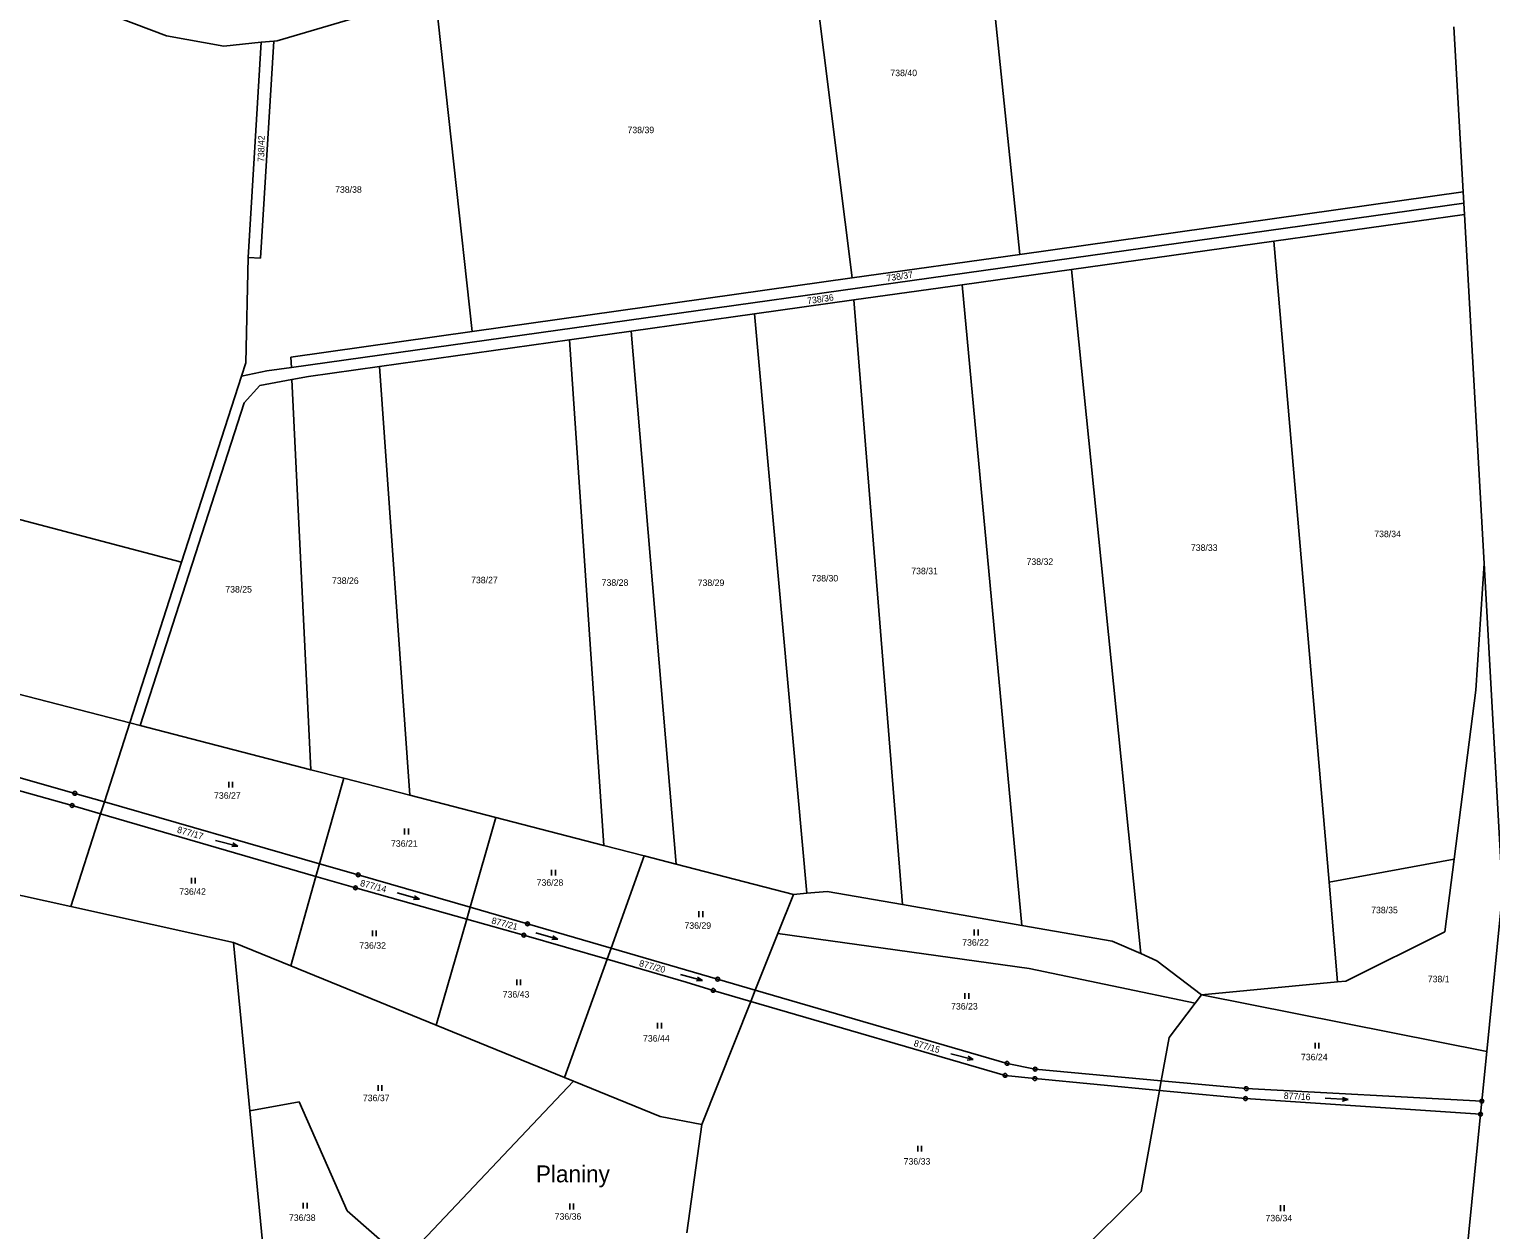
# Model space of a CAD drawing. Extents: x -791032 to -787751, y -1106872 to -1104403.
# Drawn here: x -789976.3 to -789595.2, y -1106360.1 to -1106046.8 of the extents above; entities that cross this region are included whole.
import ezdxf

# ---------------------------------------------------------------- set-up
doc = ezdxf.new("R2010")
doc.units = 0
for name, color, linetype in [('Vrstva 1', 7, 'Continuous'), ('Vrstva 14', 7, 'Continuous'), ('Vrstva 23', 7, 'Continuous'), ('Vrstva 28', 7, 'Continuous'), ('Vrstva 39', 7, 'Continuous')]:
    doc.layers.add(name, color=color, linetype=linetype)

msp = doc.modelspace()

# ---------------------------------------------------------------- linework, layer by layer
at = {"layer": 'Vrstva 1'}
for p, q in [((-789729.27, -1105996.01), (-789718.03, -1106105.57)), ((-789774.56, -1106009.37), (-789761.76, -1106111.73)), ((-789970.25, -1106037.29), (-789940.57, -1106048.55)), ((-789911.71, -1106049.84), (-789870.49, -1106037.68)), ((-789870.49, -1106037.68), (-789860.85, -1106125.71)), ((-789940.57, -1106048.55), (-789925.59, -1106051.2)), ((-789602.38, -1106089.26), (-789604.8, -1106046.21)), ((-789925.59, -1106051.2), (-789915.84, -1106050.24)), ((-789915.84, -1106050.24), (-789919.23, -1106106.35)), ((-789912.51, -1106049.92), (-789916, -1106106.52)), ((-789915.84, -1106050.24), (-789912.51, -1106049.92)), ((-789912.51, -1106049.92), (-789911.71, -1106049.84)), ((-789602.38, -1106089.26), (-789718.03, -1106105.57)), ((-789602.22, -1106092.2), (-789602.38, -1106089.26)), ((-789602.22, -1106092.2), (-789755.36, -1106113.66)), ((-789602.06, -1106095.13), (-789602.22, -1106092.2)), ((-789602.06, -1106095.13), (-789651.77, -1106102.1)), ((-789596.95, -1106186.19), (-789602.06, -1106095.13)), ((-789651.77, -1106102.1), (-789704.54, -1106109.5)), ((-789651.77, -1106102.1), (-789637.38, -1106269.41)), ((-789919.88, -1106133.86), (-789919.23, -1106106.35)), ((-789919.23, -1106106.35), (-789916, -1106106.52)), ((-789718.03, -1106105.57), (-789761.76, -1106111.73)), ((-789704.54, -1106109.5), (-789733.04, -1106113.49)), ((-789686.47, -1106288.01), (-789704.54, -1106109.5)), ((-789755.36, -1106113.66), (-789907.97, -1106135.04)), ((-789761.76, -1106111.73), (-789860.85, -1106125.71)), ((-789733.04, -1106113.49), (-789761.29, -1106117.45)), ((-789717.48, -1106280.63), (-789733.04, -1106113.49)), ((-789761.29, -1106117.45), (-789787.17, -1106121.08)), ((-789748.62, -1106275.21), (-789761.29, -1106117.45)), ((-789787.17, -1106121.08), (-789819.35, -1106125.59)), ((-789773.57, -1106272.27), (-789787.17, -1106121.08)), ((-789819.35, -1106125.59), (-789835.47, -1106127.85)), ((-789807.59, -1106264.69), (-789819.35, -1106125.59)), ((-789860.85, -1106125.71), (-789908.1, -1106132.37)), ((-789835.47, -1106127.85), (-789884.96, -1106134.79)), ((-789826.51, -1106259.79), (-789835.47, -1106127.85)), ((-789908.1, -1106132.37), (-789907.97, -1106135.04)), ((-789921, -1106137.35), (-789919.88, -1106133.86)), ((-789921, -1106137.35), (-789914.34, -1106135.94)), ((-789907.97, -1106135.04), (-789914.34, -1106135.94)), ((-789884.96, -1106134.79), (-789903.52, -1106137.39)), ((-789877.06, -1106246.71), (-789884.96, -1106134.79)), ((-789936.6, -1106185.85), (-789921, -1106137.35)), ((-789920.24, -1106144.27), (-789916.19, -1106139.81)), ((-789916.19, -1106139.81), (-789907.81, -1106138.21)), ((-789907.81, -1106138.21), (-789903.52, -1106137.39)), ((-789902.86, -1106240.04), (-789907.81, -1106138.21)), ((-789947.38, -1106228.52), (-789920.24, -1106144.27)), ((-790036.17, -1106159.75), (-789936.6, -1106185.85)), ((-789950.1, -1106227.82), (-789936.6, -1106185.85)), ((-789599.07, -1106219.3), (-789596.95, -1106186.19)), ((-789592.13, -1106272.11), (-789596.95, -1106186.19)), ((-789950.1, -1106227.82), (-790019.05, -1106209.98)), ((-789604.74, -1106263.35), (-789599.07, -1106219.3)), ((-789956.72, -1106248.41), (-789950.1, -1106227.82)), ((-789947.38, -1106228.52), (-789950.1, -1106227.82)), ((-790023.77, -1106229.41), (-789964.43, -1106246.19)), ((-789902.86, -1106240.04), (-789947.38, -1106228.52)), ((-789965.16, -1106249.35), (-790024.57, -1106232.72)), ((-789894.31, -1106242.25), (-789902.86, -1106240.04)), ((-789900.62, -1106264.57), (-789894.31, -1106242.25)), ((-789877.06, -1106246.71), (-789894.31, -1106242.25)), ((-789964.43, -1106246.19), (-789956.72, -1106248.41)), ((-789854.63, -1106252.52), (-789877.06, -1106246.71)), ((-789957.72, -1106251.51), (-789965.16, -1106249.35)), ((-789957.72, -1106251.51), (-789956.72, -1106248.41)), ((-789956.72, -1106248.41), (-789900.62, -1106264.57)), ((-789965.5, -1106275.69), (-789957.72, -1106251.51)), ((-789901.55, -1106267.86), (-789957.72, -1106251.51)), ((-789861.35, -1106275.92), (-789854.63, -1106252.52)), ((-789826.51, -1106259.79), (-789854.63, -1106252.52)), ((-789965.5, -1106275.69), (-790031.46, -1106261.12)), ((-789815.97, -1106262.52), (-789826.51, -1106259.79)), ((-789824.61, -1106286.59), (-789815.97, -1106262.52)), ((-789807.59, -1106264.69), (-789815.97, -1106262.52)), ((-789901.55, -1106267.86), (-789900.62, -1106264.57)), ((-789900.62, -1106264.57), (-789890.54, -1106267.47)), ((-789777.05, -1106272.59), (-789807.59, -1106264.69)), ((-789637.38, -1106269.41), (-789604.74, -1106263.35)), ((-789607.18, -1106282.34), (-789604.74, -1106263.35)), ((-789908.13, -1106291.16), (-789901.55, -1106267.86)), ((-789891.26, -1106270.86), (-789901.55, -1106267.86)), ((-789890.54, -1106267.47), (-789861.35, -1106275.92)), ((-789635.14, -1106295.41), (-789637.38, -1106269.41)), ((-789862.24, -1106279.01), (-789891.26, -1106270.86)), ((-789781.08, -1106282.72), (-789777.05, -1106272.59)), ((-789773.57, -1106272.27), (-789777.05, -1106272.59)), ((-789768.29, -1106271.79), (-789773.57, -1106272.27)), ((-789748.62, -1106275.21), (-789768.29, -1106271.79)), ((-789596.25, -1106313.51), (-789592.13, -1106272.11)), ((-789923.04, -1106285.07), (-789965.5, -1106275.69)), ((-789862.24, -1106279.01), (-789861.35, -1106275.92)), ((-789861.35, -1106275.92), (-789846.4, -1106280.24)), ((-789717.48, -1106280.63), (-789748.62, -1106275.21)), ((-789870.18, -1106306.67), (-789862.24, -1106279.01)), ((-789847.36, -1106283.19), (-789862.24, -1106279.01)), ((-789846.4, -1106280.24), (-789824.61, -1106286.59)), ((-789693.97, -1106284.72), (-789717.48, -1106280.63)), ((-789918.79, -1106329.04), (-789923.04, -1106285.07)), ((-789923.04, -1106285.07), (-789908.13, -1106291.16)), ((-789825.65, -1106289.49), (-789847.36, -1106283.19)), ((-789786.99, -1106297.54), (-789781.08, -1106282.72)), ((-789781.08, -1106282.72), (-789715.54, -1106291.86)), ((-789686.47, -1106288.01), (-789693.97, -1106284.72)), ((-789633.04, -1106295.21), (-789607.18, -1106282.34)), ((-789825.65, -1106289.49), (-789824.61, -1106286.59)), ((-789824.61, -1106286.59), (-789796.81, -1106294.68)), ((-789682.27, -1106289.85), (-789686.47, -1106288.01)), ((-789908.13, -1106291.16), (-789870.18, -1106306.67)), ((-789836.72, -1106320.34), (-789825.65, -1106289.49)), ((-789805.01, -1106295.47), (-789825.65, -1106289.49)), ((-789672.33, -1106300.96), (-789715.54, -1106291.86)), ((-789670.66, -1106298.75), (-789682.27, -1106289.85)), ((-789797.97, -1106297.6), (-789805.01, -1106295.47)), ((-789796.81, -1106294.68), (-789786.99, -1106297.54)), ((-789670.66, -1106298.75), (-789635.14, -1106295.41)), ((-789635.14, -1106295.41), (-789633.04, -1106295.21)), ((-789800.97, -1106332.6), (-789788.16, -1106300.46)), ((-789788.16, -1106300.46), (-789797.97, -1106297.6)), ((-789788.16, -1106300.46), (-789786.99, -1106297.54)), ((-789721.86, -1106319.78), (-789788.16, -1106300.46)), ((-789786.99, -1106297.54), (-789721.34, -1106316.65)), ((-789670.66, -1106298.75), (-789672.33, -1106300.96)), ((-789596.25, -1106313.51), (-789670.66, -1106298.75)), ((-789672.33, -1106300.96), (-789679.08, -1106309.88)), ((-789870.18, -1106306.67), (-789836.72, -1106320.34)), ((-789679.08, -1106309.88), (-789681.13, -1106321.18)), ((-789597.54, -1106326.49), (-789596.25, -1106313.51)), ((-789714.08, -1106320.62), (-789721.86, -1106319.78)), ((-789721.34, -1106316.65), (-789714.02, -1106318.15)), ((-789714.02, -1106318.15), (-789681.13, -1106321.18)), ((-789834.4, -1106321.29), (-789878.63, -1106368.04)), ((-789836.72, -1106320.34), (-789834.4, -1106321.29)), ((-789834.4, -1106321.29), (-789811.77, -1106330.54)), ((-789681.59, -1106323.7), (-789714.08, -1106320.62)), ((-789681.59, -1106323.7), (-789686.36, -1106350.1)), ((-789681.13, -1106321.18), (-789681.59, -1106323.7)), ((-789659.18, -1106325.83), (-789681.59, -1106323.7)), ((-789681.13, -1106321.18), (-789658.97, -1106323.23)), ((-789658.97, -1106323.23), (-789597.54, -1106326.49)), ((-789918.79, -1106329.04), (-789905.94, -1106326.66)), ((-789905.94, -1106326.66), (-789893.39, -1106355.11)), ((-789597.88, -1106329.92), (-789659.18, -1106325.83)), ((-789597.88, -1106329.92), (-789597.54, -1106326.49)), ((-789914.77, -1106370.55), (-789918.79, -1106329.04)), ((-789811.77, -1106330.54), (-789800.97, -1106332.6)), ((-789602.95, -1106380.85), (-789597.88, -1106329.92)), ((-789804.89, -1106360.89), (-789800.97, -1106332.6)), ((-789686.36, -1106350.1), (-789702.94, -1106366.59)), ((-789878.63, -1106368.04), (-789893.39, -1106355.11))]:
    msp.add_line(p, q, dxfattribs=at)
at = {"layer": 'Vrstva 23'}
for p, q in [((-789924.32, -1106244.66), (-789924.32, -1106243.16)), ((-789923.32, -1106243.16), (-789923.32, -1106244.66)), ((-789927.75, -1106258.522), (-789921.929, -1106259.977)), ((-789878.44, -1106256.9), (-789878.44, -1106255.4)), ((-789877.44, -1106255.4), (-789877.44, -1106256.9)), ((-789921.929, -1106259.977), (-789923.506, -1106260.098)), ((-789921.929, -1106259.977), (-789923.263, -1106259.128)), ((-789840.12, -1106267.61), (-789840.12, -1106266.11)), ((-789839.12, -1106266.11), (-789839.12, -1106267.61)), ((-789934.04, -1106269.7), (-789934.04, -1106268.2)), ((-789933.04, -1106268.2), (-789933.04, -1106269.7)), ((-789880.353, -1106272.189), (-789874.566, -1106273.77)), ((-789874.566, -1106273.77), (-789876.144, -1106273.857)), ((-789874.566, -1106273.77), (-789875.881, -1106272.893)), ((-789801.68, -1106278.46), (-789801.68, -1106276.96)), ((-789800.68, -1106276.96), (-789800.68, -1106278.46)), ((-789729.91, -1106283.25), (-789729.91, -1106281.75)), ((-789728.91, -1106281.75), (-789728.91, -1106283.25)), ((-789886.83, -1106283.49), (-789886.83, -1106281.99)), ((-789885.83, -1106281.99), (-789885.83, -1106283.49)), ((-789844.21, -1106282.601), (-789838.449, -1106284.278)), ((-789838.449, -1106284.278), (-789840.029, -1106284.339)), ((-789838.449, -1106284.278), (-789839.75, -1106283.379)), ((-789849.18, -1106296.28), (-789849.18, -1106294.78)), ((-789848.18, -1106294.78), (-789848.18, -1106296.28)), ((-789806.529, -1106293.454), (-789800.75, -1106295.065)), ((-789800.75, -1106295.065), (-789802.329, -1106295.144)), ((-789800.75, -1106295.065), (-789802.06, -1106294.181)), ((-789732.33, -1106299.83), (-789732.33, -1106298.33)), ((-789731.33, -1106298.33), (-789731.33, -1106299.83)), ((-789812.47, -1106307.56), (-789812.47, -1106306.06)), ((-789811.47, -1106306.06), (-789811.47, -1106307.56)), ((-789641.02, -1106312.77), (-789641.02, -1106311.27)), ((-789640.02, -1106311.27), (-789640.02, -1106312.77)), ((-789735.997, -1106314.122), (-789730.202, -1106315.677)), ((-789730.202, -1106315.677), (-789731.78, -1106315.771)), ((-789730.202, -1106315.677), (-789731.521, -1106314.805)), ((-789885.36, -1106323.81), (-789885.36, -1106322.31)), ((-789884.36, -1106322.31), (-789884.36, -1106323.81)), ((-789638.414, -1106325.766), (-789632.425, -1106326.113)), ((-789632.425, -1106326.113), (-789633.951, -1106326.526)), ((-789632.425, -1106326.113), (-789633.893, -1106325.527)), ((-789744.63, -1106339.62), (-789744.63, -1106338.12)), ((-789743.63, -1106338.12), (-789743.63, -1106339.62)), ((-789904.88, -1106354.49), (-789904.88, -1106352.99)), ((-789903.88, -1106352.99), (-789903.88, -1106354.49)), ((-789835.39, -1106354.74), (-789835.39, -1106353.24)), ((-789834.39, -1106353.24), (-789834.39, -1106354.74)), ((-789650.05, -1106355.17), (-789650.05, -1106353.67)), ((-789649.05, -1106353.67), (-789649.05, -1106355.17))]:
    msp.add_line(p, q, dxfattribs=at)
at = {"layer": 'Vrstva 28'}
for centre, radius in [((-789964.43, -1106246.19), 0.5), ((-789964.43, -1106246.19), 0.01), ((-789965.16, -1106249.35), 0.5), ((-789965.16, -1106249.35), 0.01), ((-789891.26, -1106270.86), 0.5), ((-789890.54, -1106267.47), 0.5), ((-789890.54, -1106267.47), 0.01), ((-789891.26, -1106270.86), 0.01), ((-789846.4, -1106280.24), 0.5), ((-789846.4, -1106280.24), 0.01), ((-789847.36, -1106283.19), 0.5), ((-789847.36, -1106283.19), 0.01), ((-789796.81, -1106294.68), 0.5), ((-789796.81, -1106294.68), 0.01), ((-789797.97, -1106297.6), 0.5), ((-789797.97, -1106297.6), 0.01), ((-789721.34, -1106316.65), 0.5), ((-789721.86, -1106319.78), 0.5), ((-789721.86, -1106319.78), 0.01), ((-789721.34, -1106316.65), 0.01), ((-789714.02, -1106318.15), 0.5), ((-789714.02, -1106318.15), 0.01), ((-789714.08, -1106320.62), 0.5), ((-789714.08, -1106320.62), 0.01), ((-789658.97, -1106323.23), 0.5), ((-789658.97, -1106323.23), 0.01), ((-789659.18, -1106325.83), 0.5), ((-789659.18, -1106325.83), 0.01), ((-789597.54, -1106326.49), 0.5), ((-789597.54, -1106326.49), 0.01), ((-789597.88, -1106329.92), 0.5), ((-789597.88, -1106329.92), 0.01)]:
    msp.add_circle(centre, radius, dxfattribs=at)

# ---------------------------------------------------------------- texts
at = {"layer": 'Vrstva 14'}
for s, p in [('738/40', (-789751.771, -1106059.07)), ('738/39', (-789820.326, -1106073.95)), ('738/38', (-789896.566, -1106089.5)), ('738/34', (-789625.592, -1106179.35)), ('738/33', (-789673.406, -1106182.93)), ('738/32', (-789716.266, -1106186.59)), ('738/26', (-789897.376, -1106191.55)), ('738/27', (-789861.103, -1106191.39)), ('738/28', (-789827.056, -1106192.05)), ('738/29', (-789802.016, -1106192.1)), ('738/30', (-789772.335, -1106190.91)), ('738/31', (-789746.33, -1106189.03)), ('738/25', (-789925.202, -1106193.8)), ('736/27', (-789928.133, -1106247.61)), ('736/21', (-789881.99, -1106260.13)), ('736/28', (-789844.016, -1106270.31)), ('736/42', (-789937.212, -1106272.67)), ('738/35', (-789626.403, -1106277.49)), ('736/29', (-789805.466, -1106281.54)), ('736/32', (-789890.256, -1106286.73)), ('736/22', (-789733.046, -1106285.95)), ('738/1', (-789611.64, -1106295.49)), ('736/43', (-789852.862, -1106299.49)), ('736/23', (-789735.946, -1106302.6)), ('736/44', (-789816.278, -1106310.97)), ('736/24', (-789644.712, -1106315.85)), ('736/37', (-789889.323, -1106326.51)), ('736/33', (-789748.307, -1106343.07)), ('736/38', (-789908.606, -1106357.75)), ('736/36', (-789839.317, -1106357.44)), ('736/34', (-789653.952, -1106357.87))]:
    msp.add_text(s, height=1.7, dxfattribs=at).set_placement(p)
for s, rotation, p in [('738/42', 88.83675, (-789915.056, -1106081.481)), ('738/37', 8.18397, (-789752.669, -1106112.638)), ('738/36', 8.18397, (-789773.342, -1106118.563)), ('877/17', 344.18331, (-789937.896, -1106256.403)), ('877/14', 345.29688, (-789890.158, -1106270.326)), ('877/21', 345.15054, (-789855.92, -1106280.115)), ('877/20', 344.78523, (-789817.411, -1106291.258)), ('877/15', 344.10429, (-789745.815, -1106312.103)), ('877/16', 356.86134, (-789649.22, -1106325.895))]:
    msp.add_text(s, height=1.7, rotation=rotation, dxfattribs=at).set_placement(p)
at = {"layer": 'Vrstva 39'}
msp.add_text('Planiny', height=4.4, dxfattribs=at).set_placement((-789844.21, -1106347.68))

doc.saveas('drawing.dxf')
